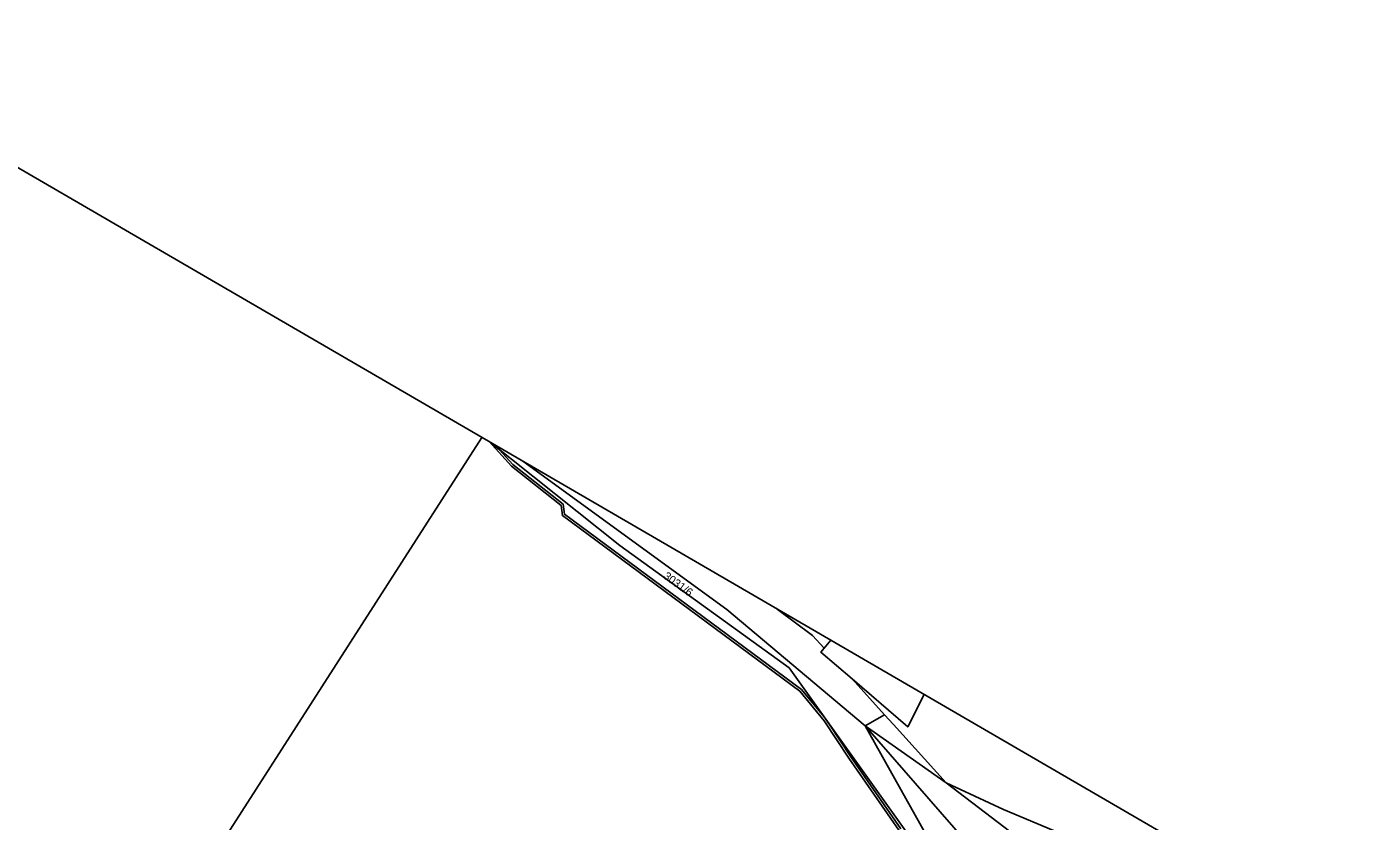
# Model space of a CAD drawing. Extents: x -621168 to -620292, y -1122748 to -1122069.
# Drawn here: x -620574.6 to -620292.4, y -1122465.1 to -1122296.3 of the extents above; entities that cross this region are included whole.
import ezdxf

# ---------------------------------------------------------------- set-up
doc = ezdxf.new("R2010")
doc.units = 0
for name, color, linetype in [('Hranice parcel', 7, 'Continuous'), ('Parcelní čísla', 7, 'Continuous'), ('Rámečky-tisk', 7, 'Continuous'), ('Vnitřní kresba', 7, 'Continuous'), ('Věcná břemena k části', 7, 'Continuous')]:
    doc.layers.add(name, color=color, linetype=linetype)

msp = doc.modelspace()

# ---------------------------------------------------------------- linework, layer by layer
at = {"layer": 'Hranice parcel'}
for p, q in [((-620548.9, -1122494.24), (-620477.85, -1122383.56)), ((-620405.21, -1122428.32), (-620403.76, -1122426.64)), ((-620379.27, -1122456.9), (-620396.46, -1122444.78)), ((-620396.46, -1122444.78), (-620369.79, -1122492.47)), ((-620379.27, -1122456.9), (-620353.42, -1122476.62))]:
    msp.add_line(p, q, dxfattribs=at)
for points in [[(-620476.11, -1122384.57), (-620448.57, -1122406.53), (-620412.63, -1122432.52), (-620369.79, -1122492.47)], [(-620396.46, -1122444.78), (-620425.84, -1122420.12), (-620469.18, -1122388.6)], [(-620415.14, -1122420.02), (-620407.66, -1122425.61), (-620405.21, -1122428.32)], [(-620405.21, -1122428.32), (-620405.92, -1122429.14), (-620399.27, -1122434.86)], [(-620383.98, -1122438.14), (-620387.43, -1122445.04), (-620399.27, -1122434.86)], [(-620399.27, -1122434.86), (-620392.37, -1122442.46), (-620390.49, -1122444.54), (-620379.27, -1122456.9)], [(-620353.03, -1122491.08), (-620367.06, -1122478.57), (-620396.46, -1122444.78)], [(-620379.27, -1122456.9), (-620367.13, -1122462.61), (-620348.06, -1122470.58), (-620333.32, -1122476.77)]]:
    msp.add_lwpolyline(points, dxfattribs=at)
at = {"layer": 'Rámečky-tisk'}
msp.add_lwpolyline([(-620441.66, -1122748.16), (-620292.37, -1122491.41), (-621018.54, -1122069.17)], dxfattribs=at)
at = {"layer": 'Vnitřní kresba'}
msp.add_line((-620392.37, -1122442.46), (-620396.46, -1122444.78), dxfattribs=at)
at = {"layer": 'Věcná břemena k části'}
for p, q in [((-620476.1, -1122384.58), (-620476.34, -1122384.43)), ((-620474.94, -1122385.25), (-620476.1, -1122384.58))]:
    msp.add_line(p, q, dxfattribs=at)
for points in [[(-620476.34, -1122384.43), (-620471.61, -1122389.68), (-620461.05, -1122398), (-620460.77, -1122400.17), (-620410.37, -1122437.43), (-620405.17, -1122443.73), (-620399.94, -1122451.7), (-620389.31, -1122467)], [(-620476.1, -1122384.58), (-620474.12, -1122386.16), (-620474.94, -1122385.25)], [(-620388.89, -1122466.72), (-620399.52, -1122451.42), (-620404.03, -1122444.55), (-620405.25, -1122442.85), (-620410.03, -1122437.07), (-620460.31, -1122399.89), (-620460.59, -1122397.74), (-620471.27, -1122389.32), (-620474.12, -1122386.16), (-620476.1, -1122384.58)]]:
    msp.add_lwpolyline(points, dxfattribs=at)

# ---------------------------------------------------------------- texts
at = {"layer": 'Parcelní čísla'}
msp.add_text('3031/6', height=1.7, rotation=324, dxfattribs=at).set_placement((-620439.48, -1122413.34))

doc.saveas('drawing.dxf')
